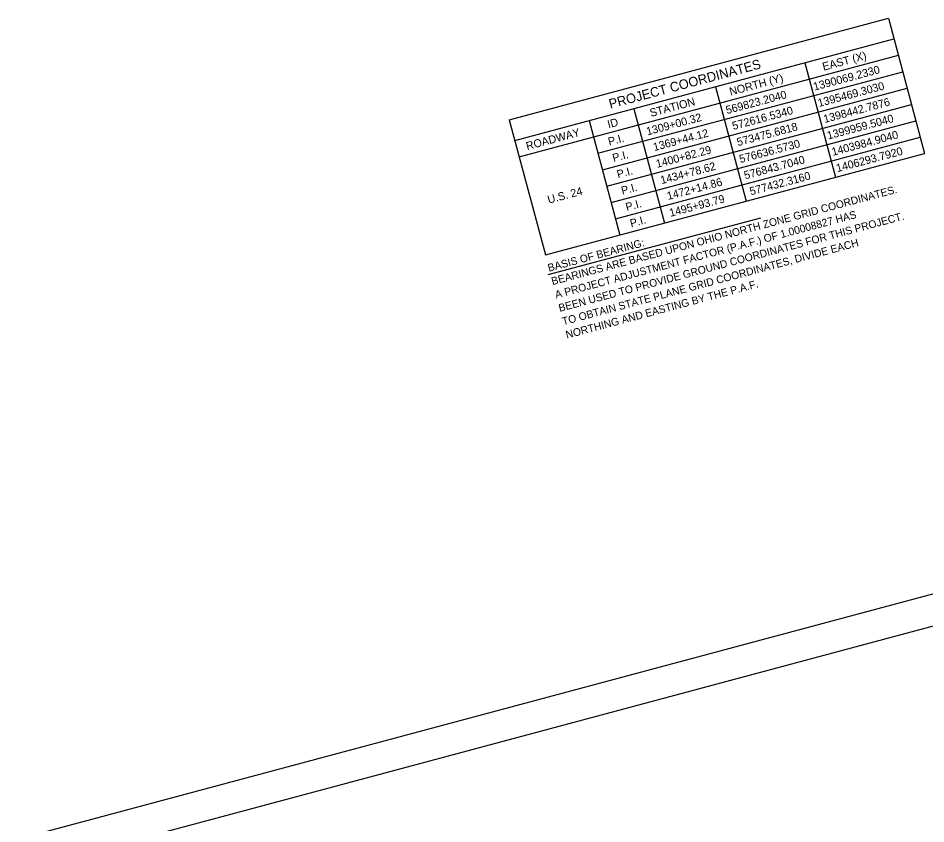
# Model space of a CAD drawing. Extents: x -361782338 to 28259792, y -263199453 to 8342113.
# Drawn here: x 1399169 to 1403593, y 579715 to 583641 of the extents above; entities that cross this region are included whole.
import ezdxf

# ---------------------------------------------------------------- set-up
doc = ezdxf.new("R2010")
doc.units = 0
for name, color, linetype in [('Level 40', 7, 'Continuous'), ('SH_Border', 7, 'Continuous'), ('SH_Cut_Line', 7, 'Continuous')]:
    doc.layers.add(name, color=color, linetype=linetype)

msp = doc.modelspace()

# ---------------------------------------------------------------- linework, layer by layer
at = {"layer": 'Level 40'}
for p, q in [((1401562.8, 583146.2), (1403410.1, 583641.2)), ((1403410.1, 583641.2), (1403586.8, 582982)), ((1401589.9, 583044.8), (1403437.3, 583539.8)), ((1401611.3, 582965.1), (1403458.6, 583460.1)), ((1403002.6, 583423.3), (1403152.1, 582865.5)), ((1401994.9, 582982.5), (1403480, 583380.4)), ((1402567.9, 583306.9), (1402717.4, 582749)), ((1402016.2, 582902.8), (1403501.3, 583300.7)), ((1402037.6, 582823.1), (1403522.7, 583221)), ((1402169.5, 583200.1), (1402319, 582642.3)), ((1401562.8, 583146.2), (1401739.4, 582487)), ((1401952.2, 583141.9), (1402101.6, 582584)), ((1402058.9, 582743.4), (1403544, 583141.4)), ((1402080.3, 582663.7), (1403565.4, 583061.7)), ((1401739.4, 582487), (1403586.8, 582982)), ((1401752.6, 582391.5), (1402788, 582668.9))]:
    msp.add_line(p, q, dxfattribs=at)
at = {"layer": 'SH_Border'}
msp.add_lwpolyline([(1399642.8, 579611), (1408915.7, 582095.7), (1410546.3, 576010.3), (1401273.4, 573525.7)], close=True, dxfattribs=at)
at = {"layer": 'SH_Cut_Line'}
msp.add_lwpolyline([(1400877.5, 573264.3), (1410730, 575904.3), (1409021.8, 582279.4), (1399169.3, 579639.4)], close=True, dxfattribs=at)

# ---------------------------------------------------------------- texts
at = {"layer": 'Level 40'}
for s, height, p in [('PROJECT COORDINATES', 46.5, (1402055.1, 583199.7)), ('EAST (X)', 39, (1403094.3, 583385)), ('1390069.2330', 39, (1403049.8, 583287.7)), ('NORTH (Y)', 39, (1402641, 583263.5)), ('1395469.3030', 39, (1403071.6, 583208.1)), ('569823.2040', 39, (1402623.5, 583173.4)), ('STATION', 39, (1402253, 583159.6)), ('1398442.7876', 39, (1403099.3, 583130.1)), ('1309+00.32', 39, (1402236, 583069.6)), ('572616.5340', 39, (1402654.5, 583096.3)), ('1399959.5040', 39, (1403116.7, 583049.4)), ('ID', 39, (1402046.6, 583104.3)), ('573475.6818', 39, (1402677.2, 583017)), ('ROADWAY', 39, (1401650, 582998)), ('1369+44.12', 39, (1402269.2, 582993.1)), ('1403984.9040', 39, (1403139.3, 582970)), ('P.I.', 39, (1402049.9, 583019.7)), ('576636.5730', 39, (1402689.2, 582934.8)), ('P.I.', 39, (1402071.2, 582940)), ('1400+82.29', 39, (1402283.1, 582911.4)), ('1406293.7920', 39, (1403161.2, 582890.5)), ('576843.7040', 39, (1402712.3, 582855.6)), ('P.I.', 39, (1402092.6, 582860.4)), ('1434+78.62', 39, (1402304.8, 582831.8)), ('1472+14.86', 39, (1402336.7, 582754.9)), ('577432.3160', 39, (1402739.9, 582777.6)), ('U.S. 24', 39, (1401754.8, 582736.9)), ('BEARINGS ARE BASED UPON OHIO NORTH ZONE GRID COORDINATES.', 37.5, (1401773.3, 582340)), ('P.I.', 39, (1402113.9, 582780.7)), ('1495+93.79', 39, (1402348.2, 582672.6)), ('P.I.', 39, (1402135.3, 582701)), ('A PROJECT ADJUSTMENT FACTOR (P.A.F.) OF 1.00008827 HAS', 37.5, (1401790.8, 582274.8)), ('BEEN USED TO PROVIDE GROUND COORDINATES FOR THIS PROJECT.', 37.5, (1401808.3, 582209.6)), ('P.I.', 39, (1402156.6, 582621.3)), ('BASIS OF BEARING:', 37.5, (1401755.9, 582405.2)), ('TO OBTAIN STATE PLANE GRID COORDINATES, DIVIDE EACH ', 37.5, (1401825.7, 582144.4)), ('NORTHING AND EASTING BY THE P.A.F.', 37.5, (1401843.2, 582079.2))]:
    msp.add_text(s, height=height, rotation=15, dxfattribs=at).set_placement(p)

doc.saveas('drawing.dxf')
